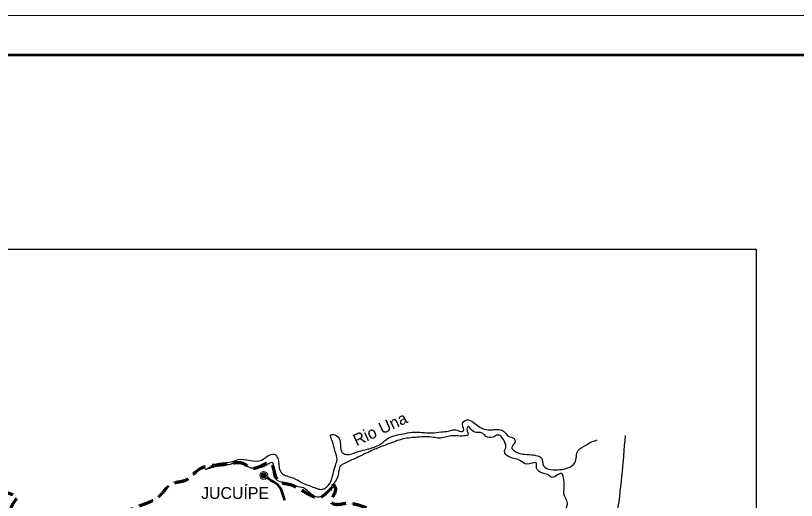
# Model space of a CAD drawing. Extents: x 512883 to 1063249, y 8784064 to 9081064.
# Drawn here: x 851806 to 950481, y 9019768 to 9081064 of the extents above; entities that cross this region are included whole.
import ezdxf

# ---------------------------------------------------------------- set-up
doc = ezdxf.new("R2010")
doc.units = 0
doc.header["$LTSCALE"] = 600
doc.linetypes.add('MEDIUM_DASHED', pattern=[4.5, 3, -1.5])
for name, color, linetype, lineweight in [('1', 7, 'Continuous', 25), ('10', 7, 'Continuous', 53), ('13', 7, 'Continuous', 90), ('3', 7, 'Continuous', 25), ('4', 7, 'Continuous', 13), ('5', 7, 'Continuous', 13), ('60', 7, 'Continuous', 25)]:
    doc.layers.add(name, color=color, linetype=linetype, lineweight=lineweight)
doc.layers.add('14', color=7, linetype='Continuous')

msp = doc.modelspace()

# ---------------------------------------------------------------- linework, layer by layer
at = {"layer": '1', "lineweight": 13}
for points in [[(512883.1, 8784063.9), (1063248.6, 8784063.9), (1063248.6, 9081063.9), (512883.1, 9081063.9)], [(537883.1, 9076063.9), (1058248.6, 9076063.9), (1058248.6, 8789063.9), (537883.1, 8789063.9)]]:
    msp.add_lwpolyline(points, close=True, dxfattribs=at)
at = {"layer": '1', "lineweight": 53}
msp.add_lwpolyline([(537883.1, 8789063.9), (1058248.6, 8789063.9), (1058248.6, 9076063.9), (537883.1, 9076063.9)], close=True, dxfattribs=at)
at = {"layer": '1'}
for points in [[(537883.1, 9076063.9), (1058248.6, 9076063.9), (1058248.6, 8789063.9), (537883.1, 8789063.9)], [(566926, 9051542.3), (945407.2, 9051542.3), (945407.2, 8818457.9), (566926, 8818457.9)]]:
    msp.add_lwpolyline(points, close=True, dxfattribs=at)
at = {"layer": '10'}
msp.add_spline([(885798.3, 9019767.7), (884973.2, 9021685), (883758, 9022515.8), (883651.9, 9022605.9)], degree=3, dxfattribs=at)
at = {"layer": '13', "linetype": 'MEDIUM_DASHED', "lineweight": 70}
for points in [[(829197.7, 9014555.7), (831473.6, 9016400), (832666.2, 9017154.5), (834733.9, 9017369.9), (835640, 9019042.3), (836236.9, 9019586.8), (837561.8, 9019737.1), (838427.1, 9019635.6), (839749.4, 9020015.5), (840270.1, 9020184.1), (841903.2, 9019730.3), (843435.9, 9019255.3), (844202.6, 9018986.5), (845489.1, 9018969.8), (846564, 9019912.3), (847141.3, 9020415), (847503.1, 9020416.2), (848201.5, 9020877.5), (849137.8, 9021631.8), (849378.7, 9021653.5), (851009.8, 9020657.6), (851917.3, 9020333.2), (851204.2, 9018711.4), (851722.8, 9017284.2), (851463.5, 9016311.1), (851528.3, 9016051.6), (853343.4, 9016311.1), (853862, 9014494.6), (854510.2, 9013456.6), (856519.7, 9014819), (859436.7, 9015467.7), (863390.8, 9016246.2), (864298.3, 9017478.8), (865141, 9018062.7), (866956, 9018906), (870290.9, 9020619.3), (871354.3, 9021775.5), (873540.1, 9022444.2), (874876.6, 9023632.2), (878429.5, 9024355.4), (880633.5, 9024420.3), (881745.7, 9023840.8), (883985, 9024525.5), (884931.5, 9022281.3), (886399.3, 9021809.7), (890479.7, 9020270.3), (891416.2, 9021016.7), (892059.7, 9021678.2)], [(896159.6, 9018825.1), (893440.4, 9019354.2), (892436.9, 9019225.7), (891730.7, 9019473.9), (891903.7, 9020184), (892232, 9021395.4), (891946.9, 9021863.4)]]:
    msp.add_spline(points, degree=3, dxfattribs=at)
at = {"layer": '3'}
msp.add_lwpolyline([(537883.1, 9076063.9), (1058248.6, 9076063.9), (1058248.6, 8789063.9), (537883.1, 8789063.9)], close=True, dxfattribs=at)
at = {"layer": '4', "lineweight": 25}
for points in [[(875966.3, 9023742.7), (876845.3, 9024225.5), (877525.8, 9024478.1), (879031.6, 9024629.1), (879892.5, 9024924), (882868, 9024850.1), (883885.8, 9025500.3), (884628.7, 9025565.3), (885064, 9024377.3), (885172.1, 9023689), (885398, 9023251.5), (886872.3, 9022609.3), (888004.7, 9021986.9), (889215.7, 9021531.7), (890586.3, 9021181.4), (891502.7, 9021914.7), (891931.5, 9023126.5), (892221.1, 9024191.7), (892434.1, 9024922.8), (892181.4, 9025965.4), (891804.9, 9027299.7), (891635.8, 9028050.5), (892380.6, 9027948.5), (892879.8, 9026426.7), (893148.7, 9025739), (893572.6, 9025573.4), (895015.9, 9025911.9), (896839.5, 9026397.8), (897959.5, 9026902.2), (898936, 9027656.7), (900779.2, 9028184.3), (901902.4, 9028396.6), (903189.1, 9028359.1), (904395.7, 9028300.3), (905620.3, 9028429.5), (906463.2, 9028536.6), (907124.9, 9028684.8), (907789.2, 9028582.6), (908232.6, 9028479.7), (908412.5, 9028563.7), (908263.5, 9029314.5), (908839.4, 9029942.4), (909666.9, 9029632.1), (911002.8, 9028780.8), (912109.2, 9028700.9), (912872.7, 9028724.2), (913477.9, 9028517.5), (914107.9, 9027893.5), (914794.7, 9027582.7), (914919.9, 9027165.7), (914505.7, 9026454.8), (914872.3, 9026017.8), (915901.7, 9025624.6), (916987.9, 9025544.7), (917551.5, 9025463), (918238.1, 9025173.1), (918531, 9024130.6), (919440.5, 9023674.4), (920586.3, 9023657.3), (921609, 9023869.2), (922466.3, 9024498.1), (922890.9, 9026085.4), (923968.6, 9026777.6), (924687.3, 9027218.1), (924967.9, 9027281.6), (925287.9, 9027428.8)], [(921127.1, 9022010.4), (920752.4, 9023177.8), (919471.5, 9022693.7), (919268.6, 9022860), (918117.7, 9023336.3), (917650, 9023835.6), (917582.3, 9024503.2), (916418.4, 9024332.5), (915609.4, 9024789), (914258, 9025222.8), (913586.5, 9025971.9), (913781.2, 9026536), (913634.3, 9027099), (913224.5, 9027807.2), (912739.6, 9028035.1), (912159.5, 9027782.8), (911234.1, 9027863.3), (910848.1, 9028237.7), (909497.6, 9028588.1), (908989.1, 9029129.1), (908852.6, 9028753), (908941.1, 9028022.9), (908640.5, 9027938.4), (907776.5, 9027914.8), (906872.1, 9027911.8), (905307.5, 9027635.5), (904602.9, 9027737.6), (902613, 9027752), (900786.4, 9027537.4), (898824.2, 9026863.3), (897743.2, 9026463.3), (896223.2, 9025790.6), (894643.8, 9025034.2), (893284, 9024403.8), (892904.7, 9024173), (892538.3, 9022773.7), (891846.7, 9021707.2), (891432, 9021038), (889974.3, 9020177.7), (889166.2, 9020550.7), (888192.8, 9021340.6), (887266.2, 9021525.4), (886257.6, 9021856.1), (884906.2, 9022289.9), (884435.6, 9023039.7), (884425, 9023999.6), (884298.6, 9024520.9), (883418, 9024184.1), (882195.9, 9023825.4), (881794, 9023824.1), (880926.3, 9024134.3), (879634.7, 9024610.2), (878934.5, 9024315.7), (877950.4, 9024249.9), (876968.4, 9023996.3), (875826, 9023700.5), (875966.3, 9023742.7)], [(901775.1, 8987223), (902699.2, 8987267.7), (903381.6, 8987353.4), (903745.9, 8987125), (904216, 8986417), (904742.9, 8986022.2), (904975.1, 8986836.8), (904846.2, 8987587.7), (905358.8, 8988486.7), (906193.7, 8989324.1), (906819.3, 8990912.1), (908413, 8994005.8), (909378, 8995803.6), (909823.6, 8997307.5), (910391.9, 8998624.1), (911240.2, 9000066.7), (912825.4, 9002116.9), (913573.4, 9003538.4), (914627.5, 9004543.5), (915816.5, 9006070.7), (916949.4, 9007222.1), (917364.1, 9007891.3), (917588.9, 9009373.6), (918101, 9010314.4), (918646, 9011923), (919238.3, 9012884.8), (919495.7, 9013240.4), (920353.7, 9013806.7), (920562, 9014955.1), (920543.8, 9016603.6), (920872.3, 9017794.2), (921207.5, 9018379.6), (921515.4, 9019611.8), (921165.5, 9020361.9), (921133.3, 9021447), (921127.1, 9022010.4)]]:
    msp.add_spline(points, degree=3, dxfattribs=at)
at = {"layer": '5'}
for p, q in [((882828.3, 9022937.2), (883493.1, 9022937.2)), ((882828.9, 9022907.2), (883492.8, 9022907.2)), ((882830.4, 9022967.2), (883491, 9022967.2)), ((882831.9, 9022877.2), (883489.5, 9022877.2)), ((882835.2, 9022997.2), (883486.2, 9022997.2)), ((882843.3, 9023027.2), (883478.1, 9023027.2)), ((882854.1, 9023057.2), (883467.3, 9023057.5)), ((882868.5, 9023087.2), (883453.2, 9023087.2)), ((882886.8, 9023117.2), (883434.9, 9023117.2)), ((882910.8, 9023147.2), (883411.2, 9023147.2)), ((882939.9, 9023177.2), (883381.5, 9023177.2)), ((882979.5, 9023207.2), (883341.9, 9023207.2)), ((883036.8, 9023237.2), (883284.6, 9023237.2)), ((882837.9, 9022847.2), (883483.5, 9022847.2)), ((882846.9, 9022817.2), (883474.5, 9022817.2)), ((882859.5, 9022787.2), (883462.2, 9022787.5)), ((882875.4, 9022757.2), (883446, 9022757.2)), ((882896.1, 9022727.2), (883425.6, 9022727.5)), ((882921.3, 9022696.9), (883400.4, 9022697.2)), ((882954.6, 9022667.2), (883366.8, 9022667.2)), ((882999.6, 9022637.2), (883321.8, 9022637.2)), ((883073.4, 9022607.2), (883247.7, 9022607.2))]:
    msp.add_line(p, q, dxfattribs=at)
for radius in [506.1, 332.9]:
    msp.add_circle((883160.8, 9022928.2), radius, dxfattribs=at)
at = {"layer": '60'}
for points in [[(875966.3, 9023742.7), (876845.3, 9024225.5), (877525.8, 9024478.1), (879031.6, 9024629.1), (879892.5, 9024924), (882868, 9024850.1), (883885.8, 9025500.3), (884628.7, 9025565.3), (885064, 9024377.3), (885172.1, 9023689), (885398, 9023251.5), (886872.3, 9022609.3), (888004.7, 9021986.9), (889215.7, 9021531.7), (890586.3, 9021181.4), (891502.7, 9021914.7), (891931.5, 9023126.5), (892221.1, 9024191.7), (892434.1, 9024922.8), (892181.4, 9025965.4), (891804.9, 9027299.7), (891635.8, 9028050.5), (892380.6, 9027948.5), (892879.8, 9026426.7), (893148.7, 9025739), (893572.6, 9025573.4), (895015.9, 9025911.9), (896839.5, 9026397.8), (897959.5, 9026902.2), (898936, 9027656.7), (900779.2, 9028184.3), (901902.4, 9028396.6), (903189.1, 9028359.1), (904395.7, 9028300.3), (905620.3, 9028429.5), (906463.2, 9028536.6), (907124.9, 9028684.8), (907789.2, 9028582.6), (908232.6, 9028479.7), (908412.5, 9028563.7), (908263.5, 9029314.5), (908839.4, 9029942.4), (909666.9, 9029632.1), (911002.8, 9028780.8), (912109.2, 9028700.9), (912872.7, 9028724.2), (913477.9, 9028517.5), (914107.9, 9027893.5), (914794.7, 9027582.7), (914919.9, 9027165.7), (914505.7, 9026454.8), (914872.3, 9026017.8), (915901.7, 9025624.6), (916987.9, 9025544.7), (917551.5, 9025463), (918238.1, 9025173.1), (918531, 9024130.6), (919440.5, 9023674.4), (920586.3, 9023657.3), (921609, 9023869.2), (922466.3, 9024498.1), (922890.9, 9026085.4), (923968.6, 9026777.6), (924687.3, 9027218.1), (924967.9, 9027281.6), (925287.9, 9027428.8)], [(875966.3, 9023742.7), (876845.3, 9024225.5), (877525.8, 9024478.1), (879031.6, 9024629.1), (879892.5, 9024924), (882868, 9024850.1), (883885.8, 9025500.3), (884628.7, 9025565.3), (885064, 9024377.3), (885172.1, 9023689), (885398, 9023251.5), (886872.3, 9022609.3), (888004.7, 9021986.9), (889215.7, 9021531.7), (890586.3, 9021181.4), (891502.7, 9021914.7), (891931.5, 9023126.5), (892221.1, 9024191.7), (892434.1, 9024922.8), (892181.4, 9025965.4), (891804.9, 9027299.7), (891635.8, 9028050.5), (892380.6, 9027948.5), (892879.8, 9026426.7), (893148.7, 9025739), (893572.6, 9025573.4), (895015.9, 9025911.9), (896839.5, 9026397.8), (897959.5, 9026902.2), (898936, 9027656.7), (900779.2, 9028184.3), (901902.4, 9028396.6), (903189.1, 9028359.1), (904395.7, 9028300.3), (905620.3, 9028429.5), (906463.2, 9028536.6), (907124.9, 9028684.8), (907789.2, 9028582.6), (908232.6, 9028479.7), (908412.5, 9028563.7), (908263.5, 9029314.5), (908839.4, 9029942.4), (909666.9, 9029632.1), (911002.8, 9028780.8), (912109.2, 9028700.9), (912872.7, 9028724.2), (913477.9, 9028517.5), (914107.9, 9027893.5), (914794.7, 9027582.7), (914919.9, 9027165.7), (914505.7, 9026454.8), (914872.3, 9026017.8), (915901.7, 9025624.6), (916987.9, 9025544.7), (917551.5, 9025463), (918238.1, 9025173.1), (918531, 9024130.6), (919440.5, 9023674.4), (920586.3, 9023657.3), (921609, 9023869.2), (922466.3, 9024498.1), (922890.9, 9026085.4), (923968.6, 9026777.6), (924687.3, 9027218.1), (924967.9, 9027281.6), (925287.9, 9027428.8)], [(921127.1, 9022010.4), (920752.4, 9023177.8), (919471.5, 9022693.7), (919268.6, 9022860), (918117.7, 9023336.3), (917650, 9023835.6), (917582.3, 9024503.2), (916418.4, 9024332.5), (915609.4, 9024789), (914258, 9025222.8), (913586.5, 9025971.9), (913781.2, 9026536), (913634.3, 9027099), (913224.5, 9027807.2), (912739.6, 9028035.1), (912159.5, 9027782.8), (911234.1, 9027863.3), (910848.1, 9028237.7), (909497.6, 9028588.1), (908989.1, 9029129.1), (908852.6, 9028753), (908941.1, 9028022.9), (908640.5, 9027938.4), (907776.5, 9027914.8), (906872.1, 9027911.8), (905307.5, 9027635.5), (904602.9, 9027737.6), (902613, 9027752), (900786.4, 9027537.4), (898824.2, 9026863.3), (897743.2, 9026463.3), (896223.2, 9025790.6), (894643.8, 9025034.2), (893284, 9024403.8), (892904.7, 9024173), (892538.3, 9022773.7), (891846.7, 9021707.2), (891432, 9021038), (889974.3, 9020177.7), (889166.2, 9020550.7), (888192.8, 9021340.6), (887266.2, 9021525.4), (886257.6, 9021856.1), (884906.2, 9022289.9), (884435.6, 9023039.7), (884425, 9023999.6), (884298.6, 9024520.9), (883418, 9024184.1), (882195.9, 9023825.4), (881794, 9023824.1), (880926.3, 9024134.3), (879634.7, 9024610.2), (878934.5, 9024315.7), (877950.4, 9024249.9), (876968.4, 9023996.3), (875826, 9023700.5), (875966.3, 9023742.7)], [(921127.1, 9022010.4), (920752.4, 9023177.8), (919471.5, 9022693.7), (919268.6, 9022860), (918117.7, 9023336.3), (917650, 9023835.6), (917582.3, 9024503.2), (916418.4, 9024332.5), (915609.4, 9024789), (914258, 9025222.8), (913586.5, 9025971.9), (913781.2, 9026536), (913634.3, 9027099), (913224.5, 9027807.2), (912739.6, 9028035.1), (912159.5, 9027782.8), (911234.1, 9027863.3), (910848.1, 9028237.7), (909497.6, 9028588.1), (908989.1, 9029129.1), (908852.6, 9028753), (908941.1, 9028022.9), (908640.5, 9027938.4), (907776.5, 9027914.8), (906872.1, 9027911.8), (905307.5, 9027635.5), (904602.9, 9027737.6), (902613, 9027752), (900786.4, 9027537.4), (898824.2, 9026863.3), (897743.2, 9026463.3), (896223.2, 9025790.6), (894643.8, 9025034.2), (893284, 9024403.8), (892904.7, 9024173), (892538.3, 9022773.7), (891846.7, 9021707.2), (891432, 9021038), (889974.3, 9020177.7), (889166.2, 9020550.7), (888192.8, 9021340.6), (887266.2, 9021525.4), (886257.6, 9021856.1), (884906.2, 9022289.9), (884435.6, 9023039.7), (884425, 9023999.6), (884298.6, 9024520.9), (883418, 9024184.1), (882195.9, 9023825.4), (881794, 9023824.1), (880926.3, 9024134.3), (879634.7, 9024610.2), (878934.5, 9024315.7), (877950.4, 9024249.9), (876968.4, 9023996.3), (875826, 9023700.5), (875966.3, 9023742.7)], [(928828.8, 9027989.5), (927727.3, 9017705.9), (905698.2, 8975836.8), (863108.4, 8926255), (823455.9, 8876673.2), (798489.5, 8846556.8), (787107.7, 8828193.2)], [(928828.8, 9027989.5), (927727.3, 9017705.9), (905698.2, 8975836.8), (863108.4, 8926255), (823455.9, 8876673.2), (798489.5, 8846556.8), (787107.7, 8828193.2)], [(901775.1, 8987223), (902699.2, 8987267.7), (903381.6, 8987353.4), (903745.9, 8987125), (904216, 8986417), (904742.9, 8986022.2), (904975.1, 8986836.8), (904846.2, 8987587.7), (905358.8, 8988486.7), (906193.7, 8989324.1), (906819.3, 8990912.1), (908413, 8994005.8), (909378, 8995803.6), (909823.6, 8997307.5), (910391.9, 8998624.1), (911240.2, 9000066.7), (912825.4, 9002116.9), (913573.4, 9003538.4), (914627.5, 9004543.5), (915816.5, 9006070.7), (916949.4, 9007222.1), (917364.1, 9007891.3), (917588.9, 9009373.6), (918101, 9010314.4), (918646, 9011923), (919238.3, 9012884.8), (919495.7, 9013240.4), (920353.7, 9013806.7), (920562, 9014955.1), (920543.8, 9016603.6), (920872.3, 9017794.2), (921207.5, 9018379.6), (921515.4, 9019611.8), (921165.5, 9020361.9), (921133.3, 9021447), (921127.1, 9022010.4)], [(901775.1, 8987223), (902699.2, 8987267.7), (903381.6, 8987353.4), (903745.9, 8987125), (904216, 8986417), (904742.9, 8986022.2), (904975.1, 8986836.8), (904846.2, 8987587.7), (905358.8, 8988486.7), (906193.7, 8989324.1), (906819.3, 8990912.1), (908413, 8994005.8), (909378, 8995803.6), (909823.6, 8997307.5), (910391.9, 8998624.1), (911240.2, 9000066.7), (912825.4, 9002116.9), (913573.4, 9003538.4), (914627.5, 9004543.5), (915816.5, 9006070.7), (916949.4, 9007222.1), (917364.1, 9007891.3), (917588.9, 9009373.6), (918101, 9010314.4), (918646, 9011923), (919238.3, 9012884.8), (919495.7, 9013240.4), (920353.7, 9013806.7), (920562, 9014955.1), (920543.8, 9016603.6), (920872.3, 9017794.2), (921207.5, 9018379.6), (921515.4, 9019611.8), (921165.5, 9020361.9), (921133.3, 9021447), (921127.1, 9022010.4)]]:
    msp.add_spline(points, degree=3, dxfattribs=at)

# ---------------------------------------------------------------- texts
at = {"layer": '14'}
msp.add_text('Rio Una', height=1500, rotation=24.792, dxfattribs=at).set_placement((894888.7, 9026598.9))
at = {"layer": '5'}
msp.add_text('JUCUÍPE', height=1500, dxfattribs=at).set_placement((875249.5, 9019948.4))

doc.saveas('drawing.dxf')
